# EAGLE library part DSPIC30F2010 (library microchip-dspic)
dsPIC Motion Controller DSP
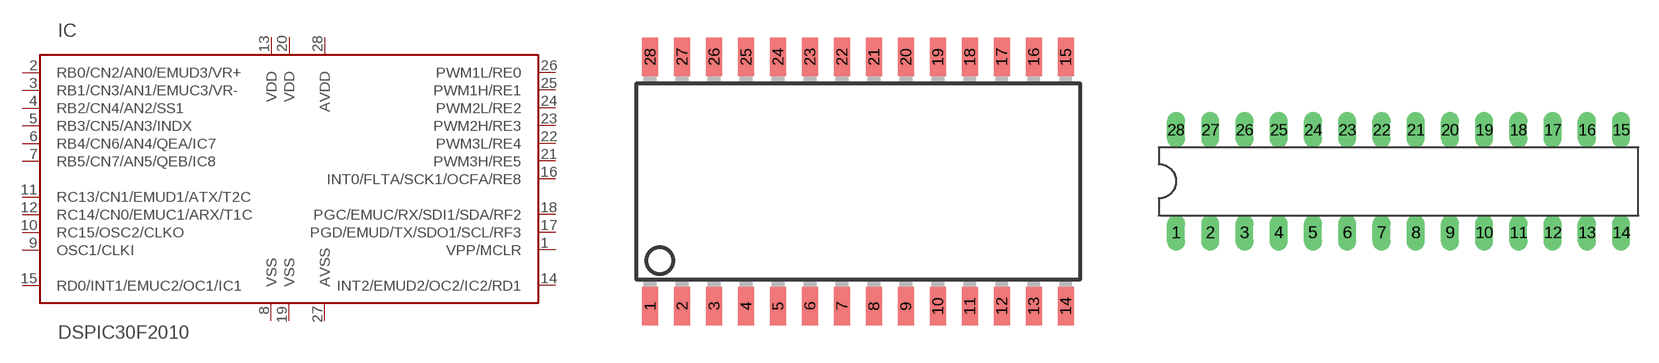
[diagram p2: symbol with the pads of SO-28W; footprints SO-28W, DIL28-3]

Designator prefix IC

## DSPIC30F2010/SOG  [SO-28W]
1  VPP/MCLR  in
2  RB0/CN2/AN0/EMUD3/VR+
3  RB1/CN3/AN1/EMUC3/VR-
4  RB2/CN4/AN2/SS1
5  RB3/CN5/AN3/INDX
6  RB4/CN6/AN4/QEA/IC7
7  RB5/CN7/AN5/QEB/IC8
8  VSS  pwr
9  OSC1/CLKI  in
10  RC15/OSC2/CLKO
11  RC13/CN1/EMUD1/ATX/T2C
12  RC14/CN0/EMUC1/ARX/T1C
13  VDD  pwr
14  INT2/EMUD2/OC2/IC2/RD1
15  RD0/INT1/EMUC2/OC1/IC1
16  INT0/FLTA/SCK1/OCFA/RE8
17  PGD/EMUD/TX/SDO1/SCL/RF3
18  PGC/EMUC/RX/SDI1/SDA/RF2
19  VSS  pwr
20  VDD  pwr
21  PWM3H/RE5
22  PWM3L/RE4
23  PWM2H/RE3
24  PWM2L/RE2
25  PWM1H/RE1
26  PWM1L/RE0
27  AVSS  pwr
28  AVDD  pwr

## DSPIC30F2010/SPG  [DIL28-3]
Pads as for SO-28W

## DSPIC30F2010/MMG  [QFN-S28-6X6]
1  RB2/CN4/AN2/SS1
2  RB3/CN5/AN3/INDX
3  RB4/CN6/AN4/QEA/IC7
4  RB5/CN7/AN5/QEB/IC8
5  VSS  pwr
6  OSC1/CLKI  in
7  RC15/OSC2/CLKO
8  RC13/CN1/EMUD1/ATX/T2C
9  RC14/CN0/EMUC1/ARX/T1C
10  VDD  pwr
11  INT2/EMUD2/OC2/IC2/RD1
12  RD0/INT1/EMUC2/OC1/IC1
13  INT0/FLTA/SCK1/OCFA/RE8
14  PGD/EMUD/TX/SDO1/SCL/RF3
15  PGC/EMUC/RX/SDI1/SDA/RF2
16  VSS  pwr
17  VDD  pwr
18  PWM3H/RE5
19  PWM3L/RE4
20  PWM2H/RE3
21  PWM2L/RE2
22  PWM1H/RE1
23  PWM1L/RE0
24  AVSS  pwr
25  AVDD  pwr
26  VPP/MCLR  in
27  RB0/CN2/AN0/EMUD3/VR+
28  RB1/CN3/AN1/EMUC3/VR-

## Footprint SO-28W (pad centres in mm)
Small Outline Wide Plastic Gull Wing 300-mil body, package type SO
smd 0.635 x 1.524: 1 -7.62,-4.953; 2 -6.35,-4.953; 3 -5.08,-4.953; 4 -3.81,-4.953; 5 -2.54,-4.953; 6 -1.27,-4.953; 7 0,-4.953; 8 1.27,-4.953; 9 2.54,-4.953; 10 3.81,-4.953; 11 5.08,-4.953; 12 6.35,-4.953; 13 7.62,-4.953; 14 8.89,-4.953; 15 8.89,4.953; 16 7.62,4.953; 17 6.35,4.953; 18 5.08,4.953; 19 3.81,4.953; 20 2.54,4.953; 21 1.27,4.953; 22 0,4.953; 23 -1.27,4.953; 24 -2.54,4.953; 25 -3.81,4.953; 26 -5.08,4.953; 27 -6.35,4.953; 28 -7.62,4.953

## Footprint DIL28-3 (pad centres in mm)
Dual In Line package type P
drill 0.813 long: 1 -16.51,-3.81; 2 -13.97,-3.81; 3 -11.43,-3.81; 4 -8.89,-3.81; 5 -6.35,-3.81; 6 -3.81,-3.81; 7 -1.27,-3.81; 8 1.27,-3.81; 9 3.81,-3.81; 10 6.35,-3.81; 11 8.89,-3.81; 12 11.43,-3.81; 13 13.97,-3.81; 14 16.51,-3.81; 15 16.51,3.81; 16 13.97,3.81; 17 11.43,3.81; 18 8.89,3.81; 19 6.35,3.81; 20 3.81,3.81; 21 1.27,3.81; 22 -1.27,3.81; 23 -3.81,3.81; 24 -6.35,3.81; 25 -8.89,3.81; 26 -11.43,3.81; 27 -13.97,3.81; 28 -16.51,3.81

## Footprint QFN-S28-6X6 (pad centres in mm)
Quad Flat No Lead
smd 0.6 x 0.4: 1 2.75,-1.95; 2 2.75,-1.3; 3 2.75,-0.65; 4 2.75,0; 5 2.75,0.65; 6 2.75,1.3; 7 2.75,1.95; 15 -2.75,1.95; 16 -2.75,1.3; 17 -2.75,0.65; 18 -2.75,0; 19 -2.75,-0.65; 20 -2.75,-1.3; 21 -2.75,-1.95
smd 0.4 x 0.6: 8 1.95,2.75; 9 1.3,2.75; 10 0.65,2.75; 11 0,2.75; 12 -0.65,2.75; 13 -1.3,2.75; 14 -1.95,2.75; 22 -1.95,-2.75; 23 -1.3,-2.75; 24 -0.65,-2.75; 25 0,-2.75; 26 0.65,-2.75; 27 1.3,-2.75; 28 1.95,-2.75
